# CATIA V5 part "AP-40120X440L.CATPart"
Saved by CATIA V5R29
Part number: AP-40120X440L
Bounding box of the stored display mesh (mm): x -220 to 220, y -60 to 60, z -20 to 20
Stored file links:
  C:\Users\Administrator\Desktop\프로젝트\Boxfold\AP-40120X440L.CATPart
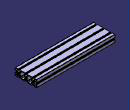
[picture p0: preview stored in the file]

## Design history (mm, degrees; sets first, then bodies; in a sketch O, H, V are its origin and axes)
Body1 (main body)
  Sketch1 on yz-plane, origin (0, 0, 0), H (0, 1, 0), V (0, 0, 1)
    point P1 (-60, -19)
    circle A1 centre (53.5, -13.5) radius 4
    circle A2 centre (53.5, 13.5) radius 4
    circle A3 centre (-53.5, -13.5) radius 4
    circle A4 centre (-53.5, 13.5) radius 4
    arc A5 centre (-38.0088, -3.1185) radius 0.3 from (-37.7966, -2.9064) to (-38.1702, -2.8656) ccw
    line L1 (-37.7966, -2.9064) -> (-37.1018, -3.6012)
    arc A6 centre (-36.8897, -3.3891) radius 0.3 from (-37.1018, -3.6012) to (-36.6868, -3.6101) ccw
    arc A7 centre (-40, 0) radius 4.9 from (-36.6868, -3.6101) to (-36.3857, -3.3086) ccw
    arc A8 centre (-36.607, -3.106) radius 0.3 from (-36.3857, -3.3086) to (-36.3949, -2.8939) ccw
    line L2 (-36.3949, -2.8939) -> (-37.0904, -2.1983)
    arc A9 centre (-36.8783, -1.9862) radius 0.3 from (-37.1314, -1.8252) to (-37.0904, -2.1983) ccw
    arc A10 centre (-40, 0) radius 3.4 from (-37.1314, -1.8252) to (-37.1323, 1.8265) ccw
    arc A11 centre (-36.8792, 1.9877) radius 0.3 from (-37.0914, 2.1998) to (-37.1323, 1.8265) ccw
    line L3 (-37.0914, 2.1998) -> (-36.396, 2.8952)
    arc A12 centre (-36.6081, 3.1073) radius 0.3 from (-36.396, 2.8952) to (-36.3869, 3.31) ccw
    arc A13 centre (-40, 0) radius 4.9 from (-36.3869, 3.31) to (-36.6881, 3.6113) ccw
    arc A14 centre (-36.8909, 3.3902) radius 0.3 from (-36.6881, 3.6113) to (-37.103, 3.6024) ccw
    line L4 (-37.103, 3.6024) -> (-37.7981, 2.9073)
    arc A15 centre (-38.0102, 3.1194) radius 0.3 from (-38.1716, 2.8665) to (-37.7981, 2.9073) ccw
    arc A16 centre (-40, 0) radius 3.4 from (-38.1716, 2.8665) to (-41.8252, 2.8686) ccw
    arc A17 centre (-41.9862, 3.1217) radius 0.3 from (-42.1983, 2.9096) to (-41.8252, 2.8686) ccw
    line L5 (-42.1983, 2.9096) -> (-42.8939, 3.6051)
    arc A18 centre (-43.106, 3.393) radius 0.3 from (-42.8939, 3.6051) to (-43.3086, 3.6143) ccw
    arc A19 centre (-40, 0) radius 4.9 from (-43.3086, 3.6143) to (-43.6101, 3.3132) ccw
    arc A20 centre (-43.3891, 3.1103) radius 0.3 from (-43.6101, 3.3132) to (-43.6012, 2.8982) ccw
    line L6 (-43.6012, 2.8982) -> (-42.9064, 2.2034)
    arc A21 centre (-43.1185, 1.9912) radius 0.3 from (-42.8656, 1.8298) to (-42.9064, 2.2034) ccw
    arc A22 centre (-40, 0) radius 3.4 from (-42.8656, 1.8298) to (-42.8665, -1.8284) ccw
    arc A23 centre (-43.1194, -1.9898) radius 0.3 from (-42.9073, -2.2019) to (-42.8665, -1.8284) ccw
    line L7 (-42.9073, -2.2019) -> (-43.6024, -2.897)
    arc A24 centre (-43.3902, -3.1091) radius 0.3 from (-43.6024, -2.897) to (-43.6113, -3.3119) ccw
    arc A25 centre (-40, 0) radius 4.9 from (-43.6113, -3.3119) to (-43.31, -3.6131) ccw
    arc A26 centre (-43.1073, -3.3919) radius 0.3 from (-43.31, -3.6131) to (-42.8952, -3.604) ccw
    line L8 (-42.8952, -3.604) -> (-42.1998, -2.9086)
    arc A27 centre (-41.9877, -3.1208) radius 0.3 from (-41.8265, -2.8677) to (-42.1998, -2.9086) ccw
    arc A28 centre (-40, 0) radius 3.4 from (-41.8265, -2.8677) to (-38.1702, -2.8656) ccw
    line L9 (39.6951, 6.0049) -> (40, 5.7)
    line L10 (40, 5.7) -> (40.3049, 6.0049)
    arc A29 centre (40, 15.5) radius 9.5 from (40.3049, 6.0049) to (47.0734, 9.1583) ccw
    arc A30 centre (46.85, 9.3585) radius 0.3 from (47.0734, 9.1583) to (47.15, 9.3585) ccw
    line L11 (47.15, 9.3585) -> (47.15, 15.7)
    arc A31 centre (46.85, 15.7) radius 0.3 from (47.15, 15.7) to (46.85, 16) ccw
    line L12 (46.85, 16) -> (44.65, 16)
    arc A32 centre (44.65, 16.5) radius 0.5 from (44.15, 16.5) to (44.65, 16) ccw
    line L13 (44.15, 16.5) -> (44.15, 19.5)
    arc A33 centre (44.65, 19.5) radius 0.5 from (44.65, 20) to (44.15, 19.5) ccw
    line L14 (44.65, 20) -> (59, 20)
    arc A34 centre (59, 19) radius 1 from (60, 19) to (59, 20) ccw
    line L15 (60, 19) -> (60, 4.65)
    arc A35 centre (59.5, 4.65) radius 0.5 from (59.5, 4.15) to (60, 4.65) ccw
    line L16 (59.5, 4.15) -> (56.5, 4.15)
    arc A36 centre (56.5, 4.65) radius 0.5 from (56, 4.65) to (56.5, 4.15) ccw
    line L17 (56, 4.65) -> (56, 6.85)
    arc A37 centre (55.7, 6.85) radius 0.3 from (56, 6.85) to (55.7, 7.15) ccw
    line L18 (55.7, 7.15) -> (49.3585, 7.15)
    arc A38 centre (49.3585, 6.85) radius 0.3 from (49.3585, 7.15) to (49.1583, 7.0734) ccw
    arc A39 centre (55.5, 0) radius 9.5 from (49.1583, 7.0734) to (46.0049, 0.3049) ccw
    line L19 (46.0049, 0.3049) -> (45.7, 0)
    line L20 (45.7, 0) -> (46.0049, -0.3049)
    arc A40 centre (55.5, 0) radius 9.5 from (46.0049, -0.3049) to (49.1583, -7.0734) ccw
    arc A41 centre (49.3585, -6.85) radius 0.3 from (49.1583, -7.0734) to (49.3585, -7.15) ccw
    line L21 (49.3585, -7.15) -> (55.7, -7.15)
    arc A42 centre (55.7, -6.85) radius 0.3 from (55.7, -7.15) to (56, -6.85) ccw
    line L22 (56, -6.85) -> (56, -4.65)
    arc A43 centre (56.5, -4.65) radius 0.5 from (56.5, -4.15) to (56, -4.65) ccw
    line L23 (56.5, -4.15) -> (59.5, -4.15)
    arc A44 centre (59.5, -4.65) radius 0.5 from (60, -4.65) to (59.5, -4.15) ccw
    line L24 (60, -4.65) -> (60, -19)
    arc A45 centre (59, -19) radius 1 from (59, -20) to (60, -19) ccw
    line L25 (59, -20) -> (44.65, -20)
    arc A46 centre (44.65, -19.5) radius 0.5 from (44.15, -19.5) to (44.65, -20) ccw
    line L26 (44.15, -19.5) -> (44.15, -16.5)
    arc A47 centre (44.65, -16.5) radius 0.5 from (44.65, -16) to (44.15, -16.5) ccw
    line L27 (44.65, -16) -> (46.85, -16)
    arc A48 centre (46.85, -15.7) radius 0.3 from (46.85, -16) to (47.15, -15.7) ccw
    line L28 (47.15, -15.7) -> (47.15, -9.3585)
    arc A49 centre (46.85, -9.3585) radius 0.3 from (47.15, -9.3585) to (47.0734, -9.1583) ccw
    arc A50 centre (40, -15.5) radius 9.5 from (47.0734, -9.1583) to (40.3049, -6.0049) ccw
    line L29 (40.3049, -6.0049) -> (40, -5.7)
    line L30 (40, -5.7) -> (39.6951, -6.0049)
    arc A51 centre (40, -15.5) radius 9.5 from (39.6951, -6.0049) to (32.9266, -9.1583) ccw
    arc A52 centre (33.15, -9.3585) radius 0.3 from (32.9266, -9.1583) to (32.85, -9.3585) ccw
    line L31 (32.85, -9.3585) -> (32.85, -15.7)
    arc A53 centre (33.15, -15.7) radius 0.3 from (32.85, -15.7) to (33.15, -16) ccw
    line L32 (33.15, -16) -> (35.35, -16)
    arc A54 centre (35.35, -16.5) radius 0.5 from (35.85, -16.5) to (35.35, -16) ccw
    line L33 (35.85, -16.5) -> (35.85, -19.5)
    arc A55 centre (35.35, -19.5) radius 0.5 from (35.35, -20) to (35.85, -19.5) ccw
    line L34 (35.35, -20) -> (4.65, -20)
    arc A56 centre (4.65, -19.5) radius 0.5 from (4.15, -19.5) to (4.65, -20) ccw
    line L35 (4.15, -19.5) -> (4.15, -16.5)
    arc A57 centre (4.65, -16.5) radius 0.5 from (4.65, -16) to (4.15, -16.5) ccw
    line L36 (4.65, -16) -> (6.85, -16)
    arc A58 centre (6.85, -15.7) radius 0.3 from (6.85, -16) to (7.15, -15.7) ccw
    line L37 (7.15, -15.7) -> (7.15, -9.3585)
    arc A59 centre (6.85, -9.3585) radius 0.3 from (7.15, -9.3585) to (7.0734, -9.1583) ccw
    arc A60 centre (0, -15.5) radius 9.5 from (7.0734, -9.1583) to (0.3049, -6.0049) ccw
    line L38 (0.3049, -6.0049) -> (0, -5.7)
    line L39 (0, -5.7) -> (-0.3049, -6.0049)
    arc A61 centre (0, -15.5) radius 9.5 from (-0.3049, -6.0049) to (-7.0734, -9.1583) ccw
    arc A62 centre (-6.85, -9.3585) radius 0.3 from (-7.0734, -9.1583) to (-7.15, -9.3585) ccw
    line L40 (-7.15, -9.3585) -> (-7.15, -15.7)
    arc A63 centre (-6.85, -15.7) radius 0.3 from (-7.15, -15.7) to (-6.85, -16) ccw
    line L41 (-6.85, -16) -> (-4.65, -16)
    arc A64 centre (-4.65, -16.5) radius 0.5 from (-4.15, -16.5) to (-4.65, -16) ccw
    line L42 (-4.15, -16.5) -> (-4.15, -19.5)
    arc A65 centre (-4.65, -19.5) radius 0.5 from (-4.65, -20) to (-4.15, -19.5) ccw
    line L43 (-4.65, -20) -> (-35.35, -20)
    arc A66 centre (-35.35, -19.5) radius 0.5 from (-35.85, -19.5) to (-35.35, -20) ccw
    line L44 (-35.85, -19.5) -> (-35.85, -16.5)
    arc A67 centre (-35.35, -16.5) radius 0.5 from (-35.35, -16) to (-35.85, -16.5) ccw
    line L45 (-35.35, -16) -> (-33.15, -16)
    arc A68 centre (-33.15, -15.7) radius 0.3 from (-33.15, -16) to (-32.85, -15.7) ccw
    line L46 (-32.85, -15.7) -> (-32.85, -9.3585)
    arc A69 centre (-33.15, -9.3585) radius 0.3 from (-32.85, -9.3585) to (-32.9266, -9.1583) ccw
    arc A70 centre (-40, -15.5) radius 9.5 from (-32.9266, -9.1583) to (-39.6951, -6.0049) ccw
    line L47 (-39.6951, -6.0049) -> (-40, -5.7)
    line L48 (-40, -5.7) -> (-40.3049, -6.0049)
    arc A71 centre (-40, -15.5) radius 9.5 from (-40.3049, -6.0049) to (-47.0734, -9.1583) ccw
    arc A72 centre (-46.85, -9.3585) radius 0.3 from (-47.0734, -9.1583) to (-47.15, -9.3585) ccw
    line L49 (-47.15, -9.3585) -> (-47.15, -15.7)
    arc A73 centre (-46.85, -15.7) radius 0.3 from (-47.15, -15.7) to (-46.85, -16) ccw
    line L50 (-46.85, -16) -> (-44.65, -16)
    arc A74 centre (-44.65, -16.5) radius 0.5 from (-44.15, -16.5) to (-44.65, -16) ccw
    line L51 (-44.15, -16.5) -> (-44.15, -19.5)
    arc A75 centre (-44.65, -19.5) radius 0.5 from (-44.65, -20) to (-44.15, -19.5) ccw
    line L52 (-44.65, -20) -> (-58, -20)
    line L53 (-58, -20) -> (-59, -20)
    arc A76 centre (-59, -19) radius 1 from (-60, -19) to (-59, -20) ccw
    line L54 (-60, -19) -> (-60, -4.65)
    arc A77 centre (-59.5, -4.65) radius 0.5 from (-59.5, -4.15) to (-60, -4.65) ccw
    line L55 (-59.5, -4.15) -> (-56.5, -4.15)
    arc A78 centre (-56.5, -4.65) radius 0.5 from (-56, -4.65) to (-56.5, -4.15) ccw
    line L56 (-56, -4.65) -> (-56, -6.85)
    arc A79 centre (-55.7, -6.85) radius 0.3 from (-56, -6.85) to (-55.7, -7.15) ccw
    line L57 (-55.7, -7.15) -> (-49.3585, -7.15)
    arc A80 centre (-49.3585, -6.85) radius 0.3 from (-49.3585, -7.15) to (-49.1583, -7.0734) ccw
    arc A81 centre (-55.5, 0) radius 9.5 from (-49.1583, -7.0734) to (-46.0049, -0.3049) ccw
    line L58 (-46.0049, -0.3049) -> (-45.7, 0)
    line L59 (-45.7, 0) -> (-46.0049, 0.3049)
    arc A82 centre (-55.5, 0) radius 9.5 from (-46.0049, 0.3049) to (-49.1583, 7.0734) ccw
    arc A83 centre (-49.3585, 6.85) radius 0.3 from (-49.1583, 7.0734) to (-49.3585, 7.15) ccw
    line L60 (-49.3585, 7.15) -> (-55.7, 7.15)
    arc A84 centre (-55.7, 6.85) radius 0.3 from (-55.7, 7.15) to (-56, 6.85) ccw
    line L61 (-56, 6.85) -> (-56, 4.65)
    arc A85 centre (-56.5, 4.65) radius 0.5 from (-56.5, 4.15) to (-56, 4.65) ccw
    line L62 (-56.5, 4.15) -> (-59.5, 4.15)
    arc A86 centre (-59.5, 4.65) radius 0.5 from (-60, 4.65) to (-59.5, 4.15) ccw
    line L63 (-60, 4.65) -> (-60, 19)
    arc A87 centre (-59, 19) radius 1 from (-59, 20) to (-60, 19) ccw
    line L64 (-59, 20) -> (-58, 20)
    line L65 (-58, 20) -> (-44.65, 20)
    arc A88 centre (-44.65, 19.5) radius 0.5 from (-44.15, 19.5) to (-44.65, 20) ccw
    line L66 (-44.15, 19.5) -> (-44.15, 16.5)
    arc A89 centre (-44.65, 16.5) radius 0.5 from (-44.65, 16) to (-44.15, 16.5) ccw
    line L67 (-44.65, 16) -> (-46.85, 16)
    arc A90 centre (-46.85, 15.7) radius 0.3 from (-46.85, 16) to (-47.15, 15.7) ccw
    line L68 (-47.15, 15.7) -> (-47.15, 9.3585)
    arc A91 centre (-46.85, 9.3585) radius 0.3 from (-47.15, 9.3585) to (-47.0734, 9.1583) ccw
    arc A92 centre (-40, 15.5) radius 9.5 from (-47.0734, 9.1583) to (-40.3049, 6.0049) ccw
    line L69 (-40.3049, 6.0049) -> (-40, 5.7)
    line L70 (-40, 5.7) -> (-39.6951, 6.0049)
    arc A93 centre (-40, 15.5) radius 9.5 from (-39.6951, 6.0049) to (-32.9266, 9.1583) ccw
    arc A94 centre (-33.15, 9.3585) radius 0.3 from (-32.9266, 9.1583) to (-32.85, 9.3585) ccw
    line L71 (-32.85, 9.3585) -> (-32.85, 15.7)
    arc A95 centre (-33.15, 15.7) radius 0.3 from (-32.85, 15.7) to (-33.15, 16) ccw
    line L72 (-33.15, 16) -> (-35.35, 16)
    arc A96 centre (-35.35, 16.5) radius 0.5 from (-35.85, 16.5) to (-35.35, 16) ccw
    line L73 (-35.85, 16.5) -> (-35.85, 19.5)
    arc A97 centre (-35.35, 19.5) radius 0.5 from (-35.35, 20) to (-35.85, 19.5) ccw
    line L74 (-35.35, 20) -> (-4.65, 20)
    arc A98 centre (-4.65, 19.5) radius 0.5 from (-4.15, 19.5) to (-4.65, 20) ccw
    line L75 (-4.15, 19.5) -> (-4.15, 16.5)
    arc A99 centre (-4.65, 16.5) radius 0.5 from (-4.65, 16) to (-4.15, 16.5) ccw
    line L76 (-4.65, 16) -> (-6.85, 16)
    arc A100 centre (-6.85, 15.7) radius 0.3 from (-6.85, 16) to (-7.15, 15.7) ccw
    line L77 (-7.15, 15.7) -> (-7.15, 9.3585)
    arc A101 centre (-6.85, 9.3585) radius 0.3 from (-7.15, 9.3585) to (-7.0734, 9.1583) ccw
    arc A102 centre (0, 15.5) radius 9.5 from (-7.0734, 9.1583) to (-0.3049, 6.0049) ccw
    line L78 (-0.3049, 6.0049) -> (0, 5.7)
    line L79 (0, 5.7) -> (0.3049, 6.0049)
    arc A103 centre (0, 15.5) radius 9.5 from (0.3049, 6.0049) to (7.0734, 9.1583) ccw
    arc A104 centre (6.85, 9.3585) radius 0.3 from (7.0734, 9.1583) to (7.15, 9.3585) ccw
    line L80 (7.15, 9.3585) -> (7.15, 15.7)
    arc A105 centre (6.85, 15.7) radius 0.3 from (7.15, 15.7) to (6.85, 16) ccw
    line L81 (6.85, 16) -> (4.65, 16)
    arc A106 centre (4.65, 16.5) radius 0.5 from (4.15, 16.5) to (4.65, 16) ccw
    line L82 (4.15, 16.5) -> (4.15, 19.5)
    arc A107 centre (4.65, 19.5) radius 0.5 from (4.65, 20) to (4.15, 19.5) ccw
    line L83 (4.65, 20) -> (35.35, 20)
    arc A108 centre (35.35, 19.5) radius 0.5 from (35.85, 19.5) to (35.35, 20) ccw
    line L84 (35.85, 19.5) -> (35.85, 16.5)
    arc A109 centre (35.35, 16.5) radius 0.5 from (35.35, 16) to (35.85, 16.5) ccw
    line L85 (35.35, 16) -> (33.15, 16)
    arc A110 centre (33.15, 15.7) radius 0.3 from (33.15, 16) to (32.85, 15.7) ccw
    line L86 (32.85, 15.7) -> (32.85, 9.3585)
    arc A111 centre (33.15, 9.3585) radius 0.3 from (32.85, 9.3585) to (32.9266, 9.1583) ccw
    arc A112 centre (40, 15.5) radius 9.5 from (32.9266, 9.1583) to (39.6951, 6.0049) ccw
    arc A113 centre (13.15, -14) radius 3 from (10.15, -14) to (13.15, -17) ccw
    line L87 (13.15, -17) -> (26.85, -17)
    arc A114 centre (26.85, -14) radius 3 from (26.85, -17) to (29.85, -14) ccw
    line L88 (29.85, -14) -> (29.85, -8.9422)
    arc A115 centre (20, -0.0053) radius 13.3 from (29.85, -8.9422) to (29.85, 8.9315) ccw
    line L89 (29.85, 8.9315) -> (29.85, 14)
    arc A116 centre (26.85, 14) radius 3 from (29.85, 14) to (26.85, 17) ccw
    line L90 (26.85, 17) -> (13.15, 17)
    arc A117 centre (13.15, 14) radius 3 from (13.15, 17) to (10.15, 14) ccw
    line L91 (10.15, 14) -> (10.15, 8.9315)
    arc A118 centre (20, -0.0053) radius 13.3 from (10.15, 8.9315) to (10.15, -8.9422) ccw
    line L92 (10.15, -8.9422) -> (10.15, -14)
    arc A119 centre (1.9912, -3.1185) radius 0.3 from (2.2034, -2.9064) to (1.8298, -2.8656) ccw
    line L93 (2.2034, -2.9064) -> (2.8982, -3.6012)
    arc A120 centre (3.1103, -3.3891) radius 0.3 from (2.8982, -3.6012) to (3.3132, -3.6101) ccw
    arc A121 centre (0, 0) radius 4.9 from (3.3132, -3.6101) to (3.6143, -3.3086) ccw
    arc A122 centre (3.393, -3.106) radius 0.3 from (3.6143, -3.3086) to (3.6051, -2.8939) ccw
    line L94 (3.6051, -2.8939) -> (2.9096, -2.1983)
    arc A123 centre (3.1217, -1.9862) radius 0.3 from (2.8686, -1.8252) to (2.9096, -2.1983) ccw
    arc A124 centre (0, 0) radius 3.4 from (2.8686, -1.8252) to (2.8677, 1.8265) ccw
    arc A125 centre (3.1208, 1.9877) radius 0.3 from (2.9086, 2.1998) to (2.8677, 1.8265) ccw
    line L95 (2.9086, 2.1998) -> (3.604, 2.8952)
    arc A126 centre (3.3919, 3.1073) radius 0.3 from (3.604, 2.8952) to (3.6131, 3.31) ccw
    arc A127 centre (0, 0) radius 4.9 from (3.6131, 3.31) to (3.3119, 3.6113) ccw
    arc A128 centre (3.1091, 3.3902) radius 0.3 from (3.3119, 3.6113) to (2.897, 3.6024) ccw
    line L96 (2.897, 3.6024) -> (2.2019, 2.9073)
    arc A129 centre (1.9898, 3.1194) radius 0.3 from (1.8284, 2.8665) to (2.2019, 2.9073) ccw
    arc A130 centre (0, 0) radius 3.4 from (1.8284, 2.8665) to (-1.8252, 2.8686) ccw
    arc A131 centre (-1.9862, 3.1217) radius 0.3 from (-2.1983, 2.9096) to (-1.8252, 2.8686) ccw
    line L97 (-2.1983, 2.9096) -> (-2.8939, 3.6051)
    arc A132 centre (-3.106, 3.393) radius 0.3 from (-2.8939, 3.6051) to (-3.3086, 3.6143) ccw
    arc A133 centre (0, 0) radius 4.9 from (-3.3086, 3.6143) to (-3.6101, 3.3132) ccw
    arc A134 centre (-3.3891, 3.1103) radius 0.3 from (-3.6101, 3.3132) to (-3.6012, 2.8982) ccw
    line L98 (-3.6012, 2.8982) -> (-2.9064, 2.2034)
    arc A135 centre (-3.1185, 1.9912) radius 0.3 from (-2.8656, 1.8298) to (-2.9064, 2.2034) ccw
    arc A136 centre (0, 0) radius 3.4 from (-2.8656, 1.8298) to (-2.8665, -1.8284) ccw
    arc A137 centre (-3.1194, -1.9898) radius 0.3 from (-2.9073, -2.2019) to (-2.8665, -1.8284) ccw
    line L99 (-2.9073, -2.2019) -> (-3.6024, -2.897)
    arc A138 centre (-3.3902, -3.1091) radius 0.3 from (-3.6024, -2.897) to (-3.6113, -3.3119) ccw
    arc A139 centre (0, 0) radius 4.9 from (-3.6113, -3.3119) to (-3.31, -3.6131) ccw
    arc A140 centre (-3.1073, -3.3919) radius 0.3 from (-3.31, -3.6131) to (-2.8952, -3.604) ccw
    line L100 (-2.8952, -3.604) -> (-2.1998, -2.9086)
    arc A141 centre (-1.9877, -3.1208) radius 0.3 from (-1.8265, -2.8677) to (-2.1998, -2.9086) ccw
    arc A142 centre (0, 0) radius 3.4 from (-1.8265, -2.8677) to (1.8298, -2.8656) ccw
    arc A143 centre (41.9912, -3.1185) radius 0.3 from (42.2034, -2.9064) to (41.8298, -2.8656) ccw
    line L101 (42.2034, -2.9064) -> (42.8982, -3.6012)
    arc A144 centre (43.1103, -3.3891) radius 0.3 from (42.8982, -3.6012) to (43.3132, -3.6101) ccw
    arc A145 centre (40, 0) radius 4.9 from (43.3132, -3.6101) to (43.6143, -3.3086) ccw
    arc A146 centre (43.393, -3.106) radius 0.3 from (43.6143, -3.3086) to (43.6051, -2.8939) ccw
    line L102 (43.6051, -2.8939) -> (42.9096, -2.1983)
    arc A147 centre (43.1217, -1.9862) radius 0.3 from (42.8686, -1.8252) to (42.9096, -2.1983) ccw
    arc A148 centre (40, 0) radius 3.4 from (42.8686, -1.8252) to (42.8677, 1.8265) ccw
    arc A149 centre (43.1208, 1.9877) radius 0.3 from (42.9086, 2.1998) to (42.8677, 1.8265) ccw
    line L103 (42.9086, 2.1998) -> (43.604, 2.8952)
    arc A150 centre (43.3919, 3.1073) radius 0.3 from (43.604, 2.8952) to (43.6131, 3.31) ccw
    arc A151 centre (40, 0) radius 4.9 from (43.6131, 3.31) to (43.3119, 3.6113) ccw
    arc A152 centre (43.1091, 3.3902) radius 0.3 from (43.3119, 3.6113) to (42.897, 3.6024) ccw
    line L104 (42.897, 3.6024) -> (42.2019, 2.9073)
    arc A153 centre (41.9898, 3.1194) radius 0.3 from (41.8284, 2.8665) to (42.2019, 2.9073) ccw
    arc A154 centre (40, 0) radius 3.4 from (41.8284, 2.8665) to (38.1748, 2.8686) ccw
    arc A155 centre (38.0138, 3.1217) radius 0.3 from (37.8017, 2.9096) to (38.1748, 2.8686) ccw
    line L105 (37.8017, 2.9096) -> (37.1061, 3.6051)
    arc A156 centre (36.894, 3.393) radius 0.3 from (37.1061, 3.6051) to (36.6914, 3.6143) ccw
    arc A157 centre (40, 0) radius 4.9 from (36.6914, 3.6143) to (36.3899, 3.3132) ccw
    arc A158 centre (36.6109, 3.1103) radius 0.3 from (36.3899, 3.3132) to (36.3988, 2.8982) ccw
    line L106 (36.3988, 2.8982) -> (37.0936, 2.2034)
    arc A159 centre (36.8815, 1.9912) radius 0.3 from (37.1344, 1.8298) to (37.0936, 2.2034) ccw
    arc A160 centre (40, 0) radius 3.4 from (37.1344, 1.8298) to (37.1335, -1.8284) ccw
    arc A161 centre (36.8806, -1.9898) radius 0.3 from (37.0927, -2.2019) to (37.1335, -1.8284) ccw
    line L107 (37.0927, -2.2019) -> (36.3976, -2.897)
    arc A162 centre (36.6098, -3.1091) radius 0.3 from (36.3976, -2.897) to (36.3887, -3.3119) ccw
    arc A163 centre (40, 0) radius 4.9 from (36.3887, -3.3119) to (36.69, -3.6131) ccw
    arc A164 centre (36.8927, -3.3919) radius 0.3 from (36.69, -3.6131) to (37.1048, -3.604) ccw
    line L108 (37.1048, -3.604) -> (37.8002, -2.9086)
    arc A165 centre (38.0123, -3.1208) radius 0.3 from (38.1735, -2.8677) to (37.8002, -2.9086) ccw
    arc A166 centre (40, 0) radius 3.4 from (38.1735, -2.8677) to (41.8298, -2.8656) ccw
    line L109 (-13.15, 17) -> (-26.85, 17)
    arc A167 centre (-26.85, 14) radius 3 from (-26.85, 17) to (-29.85, 14) ccw
    line L110 (-29.85, 14) -> (-29.85, 8.9315)
    arc A168 centre (-20, -0.0053) radius 13.3 from (-29.85, 8.9315) to (-29.85, -8.9422) ccw
    line L111 (-29.85, -8.9422) -> (-29.85, -14)
    arc A169 centre (-26.85, -14) radius 3 from (-29.85, -14) to (-26.85, -17) ccw
    line L112 (-26.85, -17) -> (-13.15, -17)
    arc A170 centre (-13.15, -14) radius 3 from (-13.15, -17) to (-10.15, -14) ccw
    line L113 (-10.15, -14) -> (-10.15, -8.9422)
    arc A171 centre (-20, -0.0053) radius 13.3 from (-10.15, -8.9422) to (-10.15, 8.9315) ccw
    line L114 (-10.15, 8.9315) -> (-10.15, 14)
    arc A172 centre (-13.15, 14) radius 3 from (-10.15, 14) to (-13.15, 17) ccw
    point P2 (-37.7966, -2.9064)
    point P3 (-38.1702, -2.8656)
    point P4 (-37.7966, -2.9064)
    point P5 (-37.1018, -3.6012)
    point P6 (-37.1018, -3.6012)
    point P7 (-36.6868, -3.6101)
    point P8 (-36.6868, -3.6101)
    point P9 (-36.3857, -3.3086)
    point P10 (-36.3857, -3.3086)
    point P11 (-36.3949, -2.8939)
    point P12 (-36.3949, -2.8939)
    point P13 (-37.0904, -2.1983)
    point P14 (-37.1314, -1.8252)
    point P15 (-37.0904, -2.1983)
    point P16 (-37.1314, -1.8252)
    point P17 (-37.1323, 1.8265)
    point P18 (-37.0914, 2.1998)
    point P19 (-37.1323, 1.8265)
    point P20 (-37.0914, 2.1998)
    point P21 (-36.396, 2.8952)
    point P22 (-36.396, 2.8952)
    point P23 (-36.3869, 3.31)
    point P24 (-36.3869, 3.31)
    point P25 (-36.6881, 3.6113)
    point P26 (-36.6881, 3.6113)
    point P27 (-37.103, 3.6024)
    point P28 (-37.103, 3.6024)
    point P29 (-37.7981, 2.9073)
    point P30 (-38.1716, 2.8665)
    point P31 (-37.7981, 2.9073)
    point P32 (-38.1716, 2.8665)
    point P33 (-41.8252, 2.8686)
    point P34 (-42.1983, 2.9096)
    point P35 (-41.8252, 2.8686)
    point P36 (-42.1983, 2.9096)
    point P37 (-42.8939, 3.6051)
    point P38 (-42.8939, 3.6051)
    point P39 (-43.3086, 3.6143)
    point P40 (-43.3086, 3.6143)
    point P41 (-43.6101, 3.3132)
    point P42 (-43.6101, 3.3132)
    point P43 (-43.6012, 2.8982)
    point P44 (-43.6012, 2.8982)
    point P45 (-42.9064, 2.2034)
    point P46 (-42.8656, 1.8298)
    point P47 (-42.9064, 2.2034)
    point P48 (-42.8656, 1.8298)
    point P49 (-42.8665, -1.8284)
    point P50 (-42.9073, -2.2019)
    point P51 (-42.8665, -1.8284)
    point P52 (-42.9073, -2.2019)
    point P53 (-43.6024, -2.897)
    point P54 (-43.6024, -2.897)
    point P55 (-43.6113, -3.3119)
    point P56 (-43.6113, -3.3119)
    point P57 (-43.31, -3.6131)
    point P58 (-43.31, -3.6131)
    point P59 (-42.8952, -3.604)
    point P60 (-42.8952, -3.604)
    point P61 (-42.1998, -2.9086)
    point P62 (-41.8265, -2.8677)
    point P63 (-42.1998, -2.9086)
    point P64 (-41.8265, -2.8677)
    point P65 (-38.1702, -2.8656)
    point P66 (39.6951, 6.0049)
    point P67 (40, 5.7)
    point P68 (40, 5.7)
    point P69 (40.3049, 6.0049)
    point P70 (40.3049, 6.0049)
    point P71 (47.0734, 9.1583)
    point P72 (47.0734, 9.1583)
    point P73 (47.15, 9.3585)
    point P74 (47.15, 9.3585)
    point P75 (47.15, 15.7)
    point P76 (47.15, 15.7)
    point P77 (46.85, 16)
    point P78 (46.85, 16)
    point P79 (44.65, 16)
    point P80 (44.15, 16.5)
    point P81 (44.65, 16)
    point P82 (44.15, 16.5)
    point P83 (44.15, 19.5)
    point P84 (44.65, 20)
    point P85 (44.15, 19.5)
    point P86 (44.65, 20)
    point P87 (59, 20)
    point P88 (60, 19)
    point P89 (59, 20)
    point P90 (60, 19)
    point P91 (60, 4.65)
    point P92 (59.5, 4.15)
    point P93 (60, 4.65)
    point P94 (59.5, 4.15)
    point P95 (56.5, 4.15)
    point P96 (56, 4.65)
    point P97 (56.5, 4.15)
    point P98 (56, 4.65)
    point P99 (56, 6.85)
    point P100 (56, 6.85)
    point P101 (55.7, 7.15)
    point P102 (55.7, 7.15)
    point P103 (49.3585, 7.15)
    point P104 (49.3585, 7.15)
    point P105 (49.1583, 7.0734)
    point P106 (49.1583, 7.0734)
    point P107 (46.0049, 0.3049)
    point P108 (46.0049, 0.3049)
    point P109 (45.7, 0)
    point P110 (45.7, 0)
    point P111 (46.0049, -0.3049)
    point P112 (46.0049, -0.3049)
    point P113 (49.1583, -7.0734)
    point P114 (49.1583, -7.0734)
    point P115 (49.3585, -7.15)
    point P116 (49.3585, -7.15)
    point P117 (55.7, -7.15)
    point P118 (55.7, -7.15)
    point P119 (56, -6.85)
    point P120 (56, -6.85)
    point P121 (56, -4.65)
    point P122 (56.5, -4.15)
    point P123 (56, -4.65)
    point P124 (56.5, -4.15)
    point P125 (59.5, -4.15)
    point P126 (60, -4.65)
    point P127 (59.5, -4.15)
    point P128 (60, -4.65)
    point P129 (60, -19)
    point P130 (59, -20)
    point P131 (60, -19)
    point P132 (59, -20)
    point P133 (44.65, -20)
    point P134 (44.15, -19.5)
    point P135 (44.65, -20)
    point P136 (44.15, -19.5)
    point P137 (44.15, -16.5)
    point P138 (44.65, -16)
    point P139 (44.15, -16.5)
    point P140 (44.65, -16)
    point P141 (46.85, -16)
    point P142 (46.85, -16)
    point P143 (47.15, -15.7)
    point P144 (47.15, -15.7)
    point P145 (47.15, -9.3585)
    point P146 (47.15, -9.3585)
    point P147 (47.0734, -9.1583)
    point P148 (47.0734, -9.1583)
    point P149 (40.3049, -6.0049)
    point P150 (40.3049, -6.0049)
    point P151 (40, -5.7)
    point P152 (40, -5.7)
    point P153 (39.6951, -6.0049)
    point P154 (39.6951, -6.0049)
    point P155 (32.9266, -9.1583)
    point P156 (32.9266, -9.1583)
    point P157 (32.85, -9.3585)
    point P158 (32.85, -9.3585)
    point P159 (32.85, -15.7)
    point P160 (32.85, -15.7)
    point P161 (33.15, -16)
    point P162 (33.15, -16)
    point P163 (35.35, -16)
    point P164 (35.85, -16.5)
    point P165 (35.35, -16)
    point P166 (35.85, -16.5)
    point P167 (35.85, -19.5)
    point P168 (35.35, -20)
    point P169 (35.85, -19.5)
    point P170 (35.35, -20)
    point P171 (4.65, -20)
    point P172 (4.15, -19.5)
    point P173 (4.65, -20)
    point P174 (4.15, -19.5)
    point P175 (4.15, -16.5)
    point P176 (4.65, -16)
    point P177 (4.15, -16.5)
    point P178 (4.65, -16)
    point P179 (6.85, -16)
    point P180 (6.85, -16)
    point P181 (7.15, -15.7)
    point P182 (7.15, -15.7)
    point P183 (7.15, -9.3585)
    point P184 (7.15, -9.3585)
    point P185 (7.0734, -9.1583)
    point P186 (7.0734, -9.1583)
    point P187 (0.3049, -6.0049)
    point P188 (0.3049, -6.0049)
    point P189 (0, -5.7)
    point P190 (0, -5.7)
    point P191 (-0.3049, -6.0049)
    point P192 (-0.3049, -6.0049)
    point P193 (-7.0734, -9.1583)
    point P194 (-7.0734, -9.1583)
    point P195 (-7.15, -9.3585)
    point P196 (-7.15, -9.3585)
    point P197 (-7.15, -15.7)
    point P198 (-7.15, -15.7)
    point P199 (-6.85, -16)
    point P200 (-6.85, -16)
    point P201 (-4.65, -16)
    point P202 (-4.15, -16.5)
    point P203 (-4.65, -16)
    point P204 (-4.15, -16.5)
    point P205 (-4.15, -19.5)
    point P206 (-4.65, -20)
    point P207 (-4.15, -19.5)
    point P208 (-4.65, -20)
    point P209 (-35.35, -20)
    point P210 (-35.85, -19.5)
    point P211 (-35.35, -20)
    point P212 (-35.85, -19.5)
    point P213 (-35.85, -16.5)
    point P214 (-35.35, -16)
    point P215 (-35.85, -16.5)
    point P216 (-35.35, -16)
    point P217 (-33.15, -16)
    point P218 (-33.15, -16)
    point P219 (-32.85, -15.7)
    point P220 (-32.85, -15.7)
    point P221 (-32.85, -9.3585)
    point P222 (-32.85, -9.3585)
    point P223 (-32.9266, -9.1583)
    point P224 (-32.9266, -9.1583)
    point P225 (-39.6951, -6.0049)
    point P226 (-39.6951, -6.0049)
    point P227 (-40, -5.7)
    point P228 (-40, -5.7)
    point P229 (-40.3049, -6.0049)
    point P230 (-40.3049, -6.0049)
    point P231 (-47.0734, -9.1583)
    point P232 (-47.0734, -9.1583)
    point P233 (-47.15, -9.3585)
    point P234 (-47.15, -9.3585)
    point P235 (-47.15, -15.7)
    point P236 (-47.15, -15.7)
    point P237 (-46.85, -16)
    point P238 (-46.85, -16)
    point P239 (-44.65, -16)
    point P240 (-44.15, -16.5)
    point P241 (-44.65, -16)
    point P242 (-44.15, -16.5)
    point P243 (-44.15, -19.5)
    point P244 (-44.65, -20)
    point P245 (-44.15, -19.5)
    point P246 (-44.65, -20)
    point P247 (-58, -20)
    point P248 (-58, -20)
    point P249 (-59, -20)
    point P250 (-60, -19)
    point P251 (-59, -20)
    point P252 (-60, -19)
    point P253 (-60, -4.65)
    point P254 (-59.5, -4.15)
    point P255 (-60, -4.65)
    point P256 (-59.5, -4.15)
    point P257 (-56.5, -4.15)
    point P258 (-56, -4.65)
    point P259 (-56.5, -4.15)
    point P260 (-56, -4.65)
    point P261 (-56, -6.85)
    point P262 (-56, -6.85)
    point P263 (-55.7, -7.15)
    point P264 (-55.7, -7.15)
    point P265 (-49.3585, -7.15)
    point P266 (-49.3585, -7.15)
    point P267 (-49.1583, -7.0734)
    point P268 (-49.1583, -7.0734)
    point P269 (-46.0049, -0.3049)
    point P270 (-46.0049, -0.3049)
    point P271 (-45.7, 0)
    point P272 (-45.7, 0)
    point P273 (-46.0049, 0.3049)
    point P274 (-46.0049, 0.3049)
    point P275 (-49.1583, 7.0734)
    point P276 (-49.1583, 7.0734)
    point P277 (-49.3585, 7.15)
    point P278 (-49.3585, 7.15)
    point P279 (-55.7, 7.15)
    point P280 (-55.7, 7.15)
    point P281 (-56, 6.85)
    point P282 (-56, 6.85)
    point P283 (-56, 4.65)
    point P284 (-56.5, 4.15)
    point P285 (-56, 4.65)
    point P286 (-56.5, 4.15)
    point P287 (-59.5, 4.15)
    point P288 (-60, 4.65)
    point P289 (-59.5, 4.15)
    point P290 (-60, 4.65)
    point P291 (-60, 19)
    point P292 (-59, 20)
    point P293 (-60, 19)
    point P294 (-59, 20)
    point P295 (-58, 20)
    point P296 (-58, 20)
    point P297 (-44.65, 20)
    point P298 (-44.15, 19.5)
    point P299 (-44.65, 20)
    point P300 (-44.15, 19.5)
    point P301 (-44.15, 16.5)
    point P302 (-44.65, 16)
    point P303 (-44.15, 16.5)
    point P304 (-44.65, 16)
    point P305 (-46.85, 16)
    point P306 (-46.85, 16)
    point P307 (-47.15, 15.7)
    point P308 (-47.15, 15.7)
    point P309 (-47.15, 9.3585)
    point P310 (-47.15, 9.3585)
    point P311 (-47.0734, 9.1583)
    point P312 (-47.0734, 9.1583)
    point P313 (-40.3049, 6.0049)
    point P314 (-40.3049, 6.0049)
    point P315 (-40, 5.7)
    point P316 (-40, 5.7)
    point P317 (-39.6951, 6.0049)
    point P318 (-39.6951, 6.0049)
    point P319 (-32.9266, 9.1583)
    point P320 (-32.9266, 9.1583)
    point P321 (-32.85, 9.3585)
    point P322 (-32.85, 9.3585)
    point P323 (-32.85, 15.7)
    point P324 (-32.85, 15.7)
    point P325 (-33.15, 16)
    point P326 (-33.15, 16)
    point P327 (-35.35, 16)
    point P328 (-35.85, 16.5)
    point P329 (-35.35, 16)
    point P330 (-35.85, 16.5)
    point P331 (-35.85, 19.5)
    point P332 (-35.35, 20)
    point P333 (-35.85, 19.5)
    point P334 (-35.35, 20)
    point P335 (-4.65, 20)
    point P336 (-4.15, 19.5)
    point P337 (-4.65, 20)
    point P338 (-4.15, 19.5)
    point P339 (-4.15, 16.5)
    point P340 (-4.65, 16)
    point P341 (-4.15, 16.5)
    point P342 (-4.65, 16)
    point P343 (-6.85, 16)
    point P344 (-6.85, 16)
    point P345 (-7.15, 15.7)
    point P346 (-7.15, 15.7)
    point P347 (-7.15, 9.3585)
    point P348 (-7.15, 9.3585)
    point P349 (-7.0734, 9.1583)
    point P350 (-7.0734, 9.1583)
    point P351 (-0.3049, 6.0049)
    point P352 (-0.3049, 6.0049)
    point P353 (0, 5.7)
    point P354 (0, 5.7)
    point P355 (0.3049, 6.0049)
    point P356 (0.3049, 6.0049)
    point P357 (7.0734, 9.1583)
    point P358 (7.0734, 9.1583)
    point P359 (7.15, 9.3585)
    point P360 (7.15, 9.3585)
    point P361 (7.15, 15.7)
    point P362 (7.15, 15.7)
    point P363 (6.85, 16)
    point P364 (6.85, 16)
    point P365 (4.65, 16)
    point P366 (4.15, 16.5)
    point P367 (4.65, 16)
    point P368 (4.15, 16.5)
    point P369 (4.15, 19.5)
    point P370 (4.65, 20)
    point P371 (4.15, 19.5)
    point P372 (4.65, 20)
    point P373 (35.35, 20)
    point P374 (35.85, 19.5)
    point P375 (35.35, 20)
    point P376 (35.85, 19.5)
    point P377 (35.85, 16.5)
    point P378 (35.35, 16)
    point P379 (35.85, 16.5)
    point P380 (35.35, 16)
    point P381 (33.15, 16)
    point P382 (33.15, 16)
    point P383 (32.85, 15.7)
    point P384 (32.85, 15.7)
    point P385 (32.85, 9.3585)
    point P386 (32.85, 9.3585)
    point P387 (32.9266, 9.1583)
    point P388 (32.9266, 9.1583)
    point P389 (39.6951, 6.0049)
    point P390 (10.15, -14)
    point P391 (13.15, -17)
    point P392 (13.15, -17)
    point P393 (26.85, -17)
    point P394 (26.85, -17)
    point P395 (29.85, -14)
    point P396 (29.85, -14)
    point P397 (29.85, -8.9422)
    point P398 (29.85, -8.9422)
    point P399 (29.85, 8.9315)
    point P400 (29.85, 8.9315)
    point P401 (29.85, 14)
    point P402 (29.85, 14)
    point P403 (26.85, 17)
    point P404 (26.85, 17)
    point P405 (13.15, 17)
    point P406 (13.15, 17)
    point P407 (10.15, 14)
    point P408 (10.15, 14)
    point P409 (10.15, 8.9315)
    point P410 (10.15, 8.9315)
    point P411 (10.15, -8.9422)
    point P412 (10.15, -8.9422)
    point P413 (10.15, -14)
    point P414 (2.2034, -2.9064)
    point P415 (1.8298, -2.8656)
    point P416 (2.2034, -2.9064)
    point P417 (2.8982, -3.6012)
    point P418 (2.8982, -3.6012)
    point P419 (3.3132, -3.6101)
    point P420 (3.3132, -3.6101)
    point P421 (3.6143, -3.3086)
    point P422 (3.6143, -3.3086)
    point P423 (3.6051, -2.8939)
    point P424 (3.6051, -2.8939)
    point P425 (2.9096, -2.1983)
    point P426 (2.8686, -1.8252)
    point P427 (2.9096, -2.1983)
    point P428 (2.8686, -1.8252)
    point P429 (2.8677, 1.8265)
    point P430 (2.9086, 2.1998)
    point P431 (2.8677, 1.8265)
    point P432 (2.9086, 2.1998)
    point P433 (3.604, 2.8952)
    point P434 (3.604, 2.8952)
    point P435 (3.6131, 3.31)
    point P436 (3.6131, 3.31)
    point P437 (3.3119, 3.6113)
    point P438 (3.3119, 3.6113)
    point P439 (2.897, 3.6024)
    point P440 (2.897, 3.6024)
    point P441 (2.2019, 2.9073)
    point P442 (1.8284, 2.8665)
    point P443 (2.2019, 2.9073)
    point P444 (1.8284, 2.8665)
    point P445 (-1.8252, 2.8686)
    point P446 (-2.1983, 2.9096)
    point P447 (-1.8252, 2.8686)
    point P448 (-2.1983, 2.9096)
    point P449 (-2.8939, 3.6051)
    point P450 (-2.8939, 3.6051)
    point P451 (-3.3086, 3.6143)
    point P452 (-3.3086, 3.6143)
    point P453 (-3.6101, 3.3132)
    point P454 (-3.6101, 3.3132)
    point P455 (-3.6012, 2.8982)
    point P456 (-3.6012, 2.8982)
    point P457 (-2.9064, 2.2034)
    point P458 (-2.8656, 1.8298)
    point P459 (-2.9064, 2.2034)
    point P460 (-2.8656, 1.8298)
    point P461 (-2.8665, -1.8284)
    point P462 (-2.9073, -2.2019)
    point P463 (-2.8665, -1.8284)
    point P464 (-2.9073, -2.2019)
    point P465 (-3.6024, -2.897)
    point P466 (-3.6024, -2.897)
    point P467 (-3.6113, -3.3119)
    point P468 (-3.6113, -3.3119)
    point P469 (-3.31, -3.6131)
    point P470 (-3.31, -3.6131)
    point P471 (-2.8952, -3.604)
    point P472 (-2.8952, -3.604)
    point P473 (-2.1998, -2.9086)
    point P474 (-1.8265, -2.8677)
    point P475 (-2.1998, -2.9086)
    point P476 (-1.8265, -2.8677)
    point P477 (1.8298, -2.8656)
    point P478 (42.2034, -2.9064)
    point P479 (41.8298, -2.8656)
    point P480 (42.2034, -2.9064)
    point P481 (42.8982, -3.6012)
    point P482 (42.8982, -3.6012)
    point P483 (43.3132, -3.6101)
    point P484 (43.3132, -3.6101)
    point P485 (43.6143, -3.3086)
    point P486 (43.6143, -3.3086)
    point P487 (43.6051, -2.8939)
    point P488 (43.6051, -2.8939)
    point P489 (42.9096, -2.1983)
    point P490 (42.8686, -1.8252)
    point P491 (42.9096, -2.1983)
    point P492 (42.8686, -1.8252)
    point P493 (42.8677, 1.8265)
    point P494 (42.9086, 2.1998)
    point P495 (42.8677, 1.8265)
    point P496 (42.9086, 2.1998)
    point P497 (43.604, 2.8952)
    point P498 (43.604, 2.8952)
    point P499 (43.6131, 3.31)
    point P500 (43.6131, 3.31)
    point P501 (43.3119, 3.6113)
    point P502 (43.3119, 3.6113)
    point P503 (42.897, 3.6024)
    point P504 (42.897, 3.6024)
    point P505 (42.2019, 2.9073)
    point P506 (41.8284, 2.8665)
    point P507 (42.2019, 2.9073)
    point P508 (41.8284, 2.8665)
    point P509 (38.1748, 2.8686)
    point P510 (37.8017, 2.9096)
    point P511 (38.1748, 2.8686)
    point P512 (37.8017, 2.9096)
    point P513 (37.1061, 3.6051)
    point P514 (37.1061, 3.6051)
    point P515 (36.6914, 3.6143)
    point P516 (36.6914, 3.6143)
    point P517 (36.3899, 3.3132)
    point P518 (36.3899, 3.3132)
    point P519 (36.3988, 2.8982)
    point P520 (36.3988, 2.8982)
    point P521 (37.0936, 2.2034)
    point P522 (37.1344, 1.8298)
    point P523 (37.0936, 2.2034)
    point P524 (37.1344, 1.8298)
    point P525 (37.1335, -1.8284)
    point P526 (37.0927, -2.2019)
    point P527 (37.1335, -1.8284)
    point P528 (37.0927, -2.2019)
    point P529 (36.3976, -2.897)
    point P530 (36.3976, -2.897)
    point P531 (36.3887, -3.3119)
    point P532 (36.3887, -3.3119)
    point P533 (36.69, -3.6131)
    point P534 (36.69, -3.6131)
    point P535 (37.1048, -3.604)
    point P536 (37.1048, -3.604)
    point P537 (37.8002, -2.9086)
    point P538 (38.1735, -2.8677)
    point P539 (37.8002, -2.9086)
    point P540 (38.1735, -2.8677)
    point P541 (41.8298, -2.8656)
    point P542 (-13.15, 17)
    point P543 (-26.85, 17)
    point P544 (-26.85, 17)
    point P545 (-29.85, 14)
    point P546 (-29.85, 14)
    point P547 (-29.85, 8.9315)
    point P548 (-29.85, 8.9315)
    point P549 (-29.85, -8.9422)
    point P550 (-29.85, -8.9422)
    point P551 (-29.85, -14)
    point P552 (-29.85, -14)
    point P553 (-26.85, -17)
    point P554 (-26.85, -17)
    point P555 (-13.15, -17)
    point P556 (-13.15, -17)
    point P557 (-10.15, -14)
    point P558 (-10.15, -14)
    point P559 (-10.15, -8.9422)
    point P560 (-10.15, -8.9422)
    point P561 (-10.15, 8.9315)
    point P562 (-10.15, 8.9315)
    point P563 (-10.15, 14)
    point P564 (-10.15, 14)
    point P565 (-13.15, 17)
    reference intersected line E1 through (0, 0) direction (0, 1) from zx-plane
    distance H L83 = 20
    distance L15 E1 = 60
    coincidence: P2 P4, P3 P65, P5 P6, P7 P8, P9 P10, P11 P12, P13 P15, P14 P16, P17 P19, P18 P20, P21 P22, P23 P24, P25 P26, P27 P28, P29 P31, P30 P32, P33 P35, P34 P36, P37 P38, P39 P40, P41 P42, P43 P44, P45 P47, P46 P48, P49 P51, P50 P52, P53 P54, P55 P56, P57 P58, P59 P60, P61 P63, P62 P64, P66 P389, P67 P68, P69 P70, P71 P72, P73 P74, P75 P76, P77 P78, P79 P81, P80 P82, P83 P85, P84 P86, P88 P90, P89 P87, P91 P93, P92 P94, P95 P97, P96 P98, P99 P100, P101 P102, P103 P104, P105 P106, P107 P108, P109 P110, P111 P112, P113 P114, P115 P116, P117 P118, P119 P120, P121 P123, P122 P124, P125 P127, P126 P128, P132 P130, P133 P135, P134 P136, P137 P139, P138 P140, P141 P142, P143 P144, P145 P146, P147 P148, P149 P150, P151 P152, P153 P154, P155 P156, P157 P158, P159 P160, P161 P162, P163 P165, P164 P166, P167 P169, P168 P170, P171 P173, P172 P174, P175 P177, P176 P178, P179 P180, P181 P182, P183 P184, P185 P186, P187 P188, P189 P190, P191 P192, P193 P194, P195 P196, P197 P198, P199 P200, P201 P203, P202 P204, P205 P207, P206 P208, P209 P211, P210 P212, P213 P215, P214 P216, P217 P218, P219 P220, P221 P222, P223 P224, P225 P226, P227 P228, P229 P230, P231 P232, P233 P234, P235 P236, P237 P238, P239 P241, P240 P242, P243 P245, P244 P246, P247 P248, P249 P251, P250 P252, P253 P255, P254 P256, P257 P259, P258 P260, P261 P262, P263 P264, P265 P266, P267 P268, P269 P270, P271 P272, P273 P274, P275 P276, P277 P278, P279 P280, P281 P282, P283 P285, P284 P286, P287 P289, P288 P290, P291 P293, P292 P294, P295 P296, P297 P299, P298 P300, P301 P303, P302 P304, P305 P306, P307 P308, P309 P310, P311 P312, P313 P314, P315 P316, P317 P318, P319 P320, P321 P322, P323 P324, P325 P326, P327 P329, P328 P330, P331 P333, P332 P334, P335 P337, P336 P338, P339 P341, P340 P342, P343 P344, P345 P346, P347 P348, P349 P350, P351 P352, P353 P354, P355 P356, P357 P358, P359 P360, P361 P362, P363 P364, P365 P367, P366 P368, P369 P371, P370 P372, P373 P375, P374 P376, P377 P379, P378 P380, P381 P382, P383 P384, P385 P386, P387 P388, P390 P413, P391 P392, P393 P394, P395 P396, P397 P398, P399 P400, P401 P402, P403 P404, P405 P406, P407 P408, P409 P410, P411 P412, P414 P416, P415 P477, P417 P418, P419 P420, P421 P422, P423 P424, P425 P427, P426 P428, P429 P431, P430 P432, P433 P434, P435 P436, P437 P438, P439 P440, P441 P443, P442 P444, P445 P447, P446 P448, P449 P450, P451 P452, P453 P454, P455 P456, P457 P459, P458 P460, P461 P463, P462 P464, P465 P466, P467 P468, P469 P470, P471 P472, P473 P475, P474 P476, P478 P480, P479 P541, P481 P482, P483 P484, P485 P486, P487 P488, P489 P491, P490 P492, P493 P495, P494 P496, P497 P498, P499 P500, P501 P502, P503 P504, P505 P507, P506 P508, P509 P511, P510 P512, P513 P514, P515 P516, P517 P518, P519 P520, P521 P523, P522 P524, P525 P527, P526 P528, P529 P530, P531 P532, P533 P534, P535 P536, P537 P539, P538 P540, P542 P565, P543 P544, P545 P546, P547 P548, P549 P550, P551 P552, P553 P554, P555 P556, P557 P558, P559 P560, P561 P562, P563 P564, P131 P129
  Pad1: profile Sketch1, direction (1, 0, 0), length 220, mirrored extent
